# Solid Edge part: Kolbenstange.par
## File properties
Username: ahadarics
Dokumentum tartalom típus: 0
Author: ahadarics
Last saved by: ahadarics
Revision: 86
Sűrűség: 0,000 kg/m^3
Pontosság: 0,990
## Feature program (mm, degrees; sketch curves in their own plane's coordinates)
base feature "unnamed BaseFeature 1"
sketch for "unnamed Protrusion 1" plane through (46.75, 0, 0) normal (1, 0, 0) x-axis (0, -1, 0)
  circle centre (0, 0) radius 6
extrude "unnamed Protrusion 1" add finite 27 along -normal
thread "Menet_1"  ThreadDepth = 16 mm
chamfer "Letörés_2" setback 0.4
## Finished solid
Body 1: solid body, 13 faces, 23 edges, 12 vertices.
  Faces by surface: plane 9, cylinder 3, cone 1
  Edges by curve: line 12, circle 11
Bounding box of the edges (mm): 325.500 x 12.000 x 12.000, from (-278.75, -6, -6) to (46.75, 6, 6).
Cylindrical faces by radius (mm): R3 x2, R6 x1
Conical faces (half-angle, radius in mm at the cone's reference point): 45 deg R2.6 x1
Planar faces by outward normal: +x 3, +z 1, -x 4, -z 1
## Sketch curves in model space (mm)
circle centre (46.75, 0, 0) radius 6
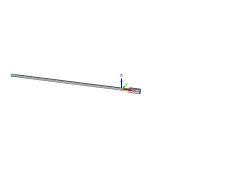
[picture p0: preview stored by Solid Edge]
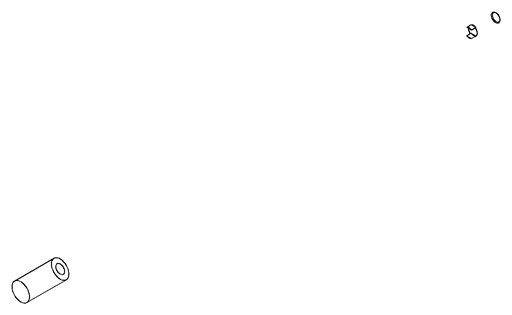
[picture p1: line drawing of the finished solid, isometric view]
